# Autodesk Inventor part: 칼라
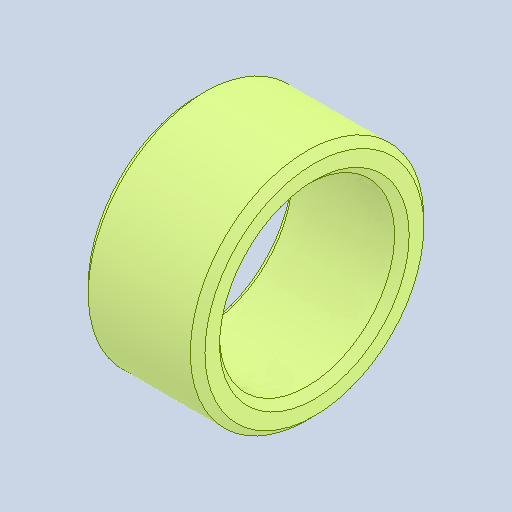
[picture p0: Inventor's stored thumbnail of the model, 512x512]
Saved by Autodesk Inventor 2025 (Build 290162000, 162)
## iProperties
Created: 2026-07
Part Number: 칼라
Material: 강철, 연강
Document SubType Name: Modeling
Designer: KDI
Density: 7.85 g/cm^3
Appearance: 기본값
Author: jhkim
Sending System: Autodesk Inventor 2027
Preprocessor: ST-DEVELOPER v20.1
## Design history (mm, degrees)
feature "솔리드1"
node "솔리드2"
